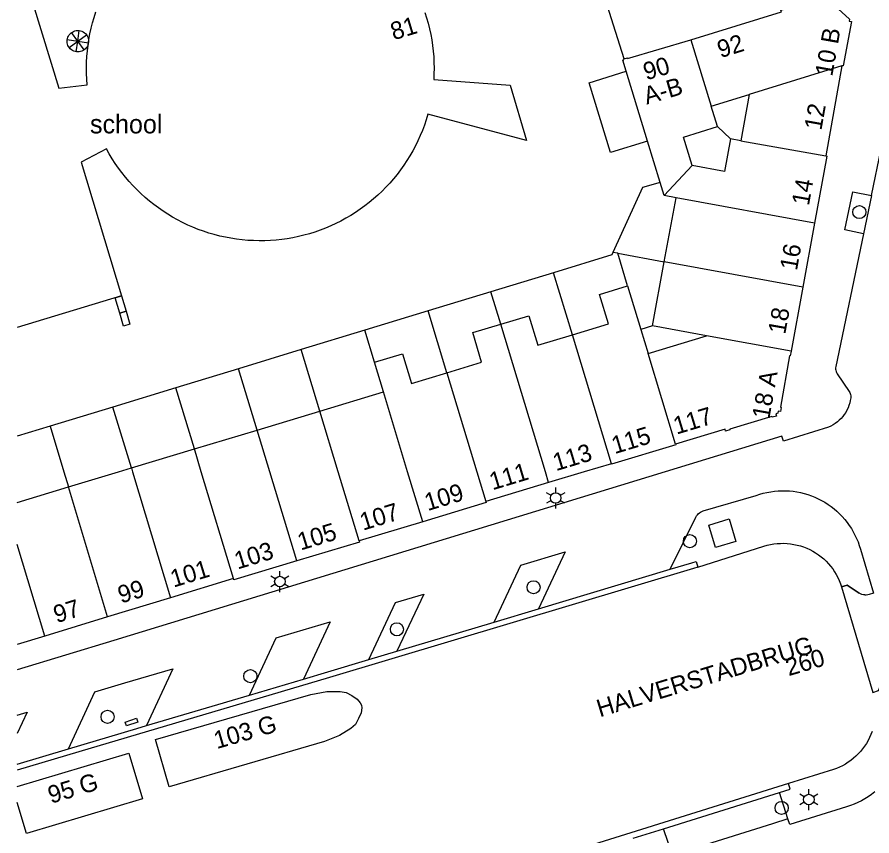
# Model space of a CAD drawing. Extents: x 122462 to 123306, y 485548 to 486417.
# Drawn here: x 122462 to 122535, y 486218.9 to 486288.9 of the extents above; entities that cross this region are included whole.
import ezdxf

# ---------------------------------------------------------------- set-up
doc = ezdxf.new("R2010")
doc.units = 0
for name, color, linetype in [('B-WE-IE-MEUBILAIR_WEGMEUBILAIR_VERKEERSBORD-S', 7, 'Continuous'), ('Level 1', 7, 'Continuous'), ('Level 10', 7, 'Continuous'), ('Level 12', 7, 'Continuous'), ('Level 14', 7, 'Continuous'), ('Level 15', 7, 'Continuous'), ('Level 17', 7, 'Continuous'), ('Level 19', 7, 'Continuous'), ('Level 2', 7, 'Continuous'), ('Level 21', 7, 'Continuous'), ('Level 32', 7, 'Continuous'), ('Level 33', 7, 'Continuous'), ('Level 4', 7, 'Continuous'), ('Level 40', 7, 'Continuous'), ('Level 50', 7, 'Continuous'), ('Level 53', 7, 'Continuous'), ('Level 62', 7, 'Continuous'), ('N meubilair putkast', 7, 'Continuous'), ('N werkgrens', 7, 'Continuous')]:
    doc.layers.add(name, color=color, linetype=linetype)

msp = doc.modelspace()

# ---------------------------------------------------------------- linework, layer by layer
at = {"layer": 'Level 1'}
for p, q in [((122532.48, 486284.697), (122531.091, 486276.988)), ((122521.32, 486281.241), (122524.568, 486282.25)), ((122524.568, 486282.25), (122523.855, 486278.292)), ((122521.859, 486279.506), (122521.32, 486281.241)), ((122516.965, 486274.72), (122515.878, 486278.265)), ((122523.855, 486278.292), (122522.953, 486278.455)), ((122517.308, 486273.601), (122516.965, 486274.72)), ((122517.303, 486267.945), (122518.31, 486273.417)), ((122518.31, 486273.417), (122517.308, 486273.601)), ((122530.14, 486271.239), (122529.132, 486265.768)), ((122516.296, 486262.474), (122517.303, 486267.945)), ((122514.176, 486265.888), (122515.298, 486262.173)), ((122529.132, 486265.768), (122528.13, 486260.319)), ((122520.897, 486261.627), (122516.296, 486262.474)), ((122515.298, 486262.173), (122515.917, 486260.122)), ((122515.917, 486260.122), (122520.897, 486261.627)), ((122493.317, 486256.833), (122492.554, 486259.36)), ((122487.892, 486255.195), (122493.317, 486256.833)), ((122482.53, 486253.576), (122487.892, 486255.195)), ((122477.168, 486251.957), (122482.53, 486253.576)), ((122471.79, 486250.333), (122477.168, 486251.957)), ((122466.413, 486248.711), (122470.686, 486250)), ((122470.686, 486250), (122471.79, 486250.333)), ((122510.47, 486250), (122507.426, 486249.085)), ((122512.785, 486250.696), (122510.47, 486250)), ((122462.03, 486247.387), (122466.413, 486248.711)), ((122507.426, 486249.085), (122502.059, 486247.469)), ((122496.669, 486245.738), (122491.245, 486244.097)), ((122480.519, 486240.89), (122475.139, 486239.25)), ((122475.139, 486239.25), (122469.765, 486237.61)), ((122469.765, 486237.61), (122464.39, 486235.969)), ((122464.39, 486235.969), (122462.03, 486235.259))]:
    msp.add_line(p, q, dxfattribs=at)
for points in [[(122519.559, 486286.91), (122527.317, 486289.297), (122527.269, 486289.449), (122530.959, 486290.59), (122531.009, 486290.409), (122531.189, 486290.459), (122533.12, 486288.679), (122533.098, 486288.51), (122533.289, 486288.479), (122532.58, 486284.679), (122532.48, 486284.697)], [(122463.413, 486289.945), (122465.586, 486282.778), (122468.027, 486283.078), (122467.989, 486283.562), (122467.967, 486284.046), (122467.96, 486284.531), (122467.97, 486285.016), (122467.995, 486285.501), (122468.036, 486285.984), (122468.093, 486286.466), (122468.166, 486286.946), (122468.254, 486287.423), (122468.358, 486287.896), (122468.477, 486288.367), (122468.612, 486288.833), (122468.761, 486289.294)], [(122496.856, 486289.255), (122497.004, 486288.793), (122497.137, 486288.326), (122497.255, 486287.856), (122497.358, 486287.382), (122497.445, 486286.904), (122497.516, 486286.425), (122497.572, 486285.943), (122497.611, 486285.459), (122497.635, 486284.975)], [(122513.879, 486285.284), (122514.149, 486285.363), (122514.16, 486285.324), (122519.559, 486286.91)], [(122514.051, 486284.225), (122513.758, 486285.18), (122513.846, 486285.207), (122513.83, 486285.269), (122513.879, 486285.284)], [(122497.635, 486284.975), (122497.643, 486284.49), (122497.636, 486284.005), (122497.612, 486283.52), (122504.133, 486283.027), (122505.539, 486278.306), (122497.114, 486280.554), (122496.974, 486280.091), (122496.819, 486279.633), (122496.649, 486279.18), (122496.465, 486278.732), (122496.266, 486278.291), (122496.052, 486277.857), (122495.825, 486277.43), (122495.584, 486277.01), (122495.33, 486276.599), (122495.062, 486276.196), (122494.782, 486275.802), (122494.489, 486275.417), (122494.183, 486275.042), (122493.865, 486274.677), (122493.536, 486274.322), (122493.196, 486273.979), (122492.844, 486273.647), (122492.482, 486273.326), (122492.109, 486273.017), (122491.727, 486272.721), (122491.335, 486272.437), (122490.935, 486272.166), (122490.525, 486271.908), (122490.108, 486271.663), (122489.683, 486271.432), (122489.25, 486271.216), (122488.811, 486271.013), (122488.365, 486270.825), (122487.914, 486270.651), (122487.457, 486270.492), (122486.995, 486270.348), (122486.529, 486270.219), (122486.058, 486270.105), (122485.585, 486270.007), (122485.108, 486269.924), (122484.629, 486269.856), (122484.148, 486269.804), (122483.665, 486269.768), (122483.182, 486269.748), (122482.698, 486269.743), (122482.215, 486269.754), (122481.732, 486269.781), (122481.25, 486269.823), (122480.769, 486269.881), (122480.291, 486269.954), (122479.816, 486270.043), (122479.343, 486270.148), (122478.874, 486270.267), (122478.41, 486270.402), (122477.95, 486270.552), (122477.495, 486270.717), (122477.046, 486270.896), (122476.603, 486271.09), (122476.166, 486271.299), (122475.736, 486271.521), (122475.314, 486271.757), (122474.9, 486272.007), (122474.494, 486272.27), (122474.096, 486272.546), (122473.708, 486272.835), (122473.33, 486273.136), (122472.961, 486273.45), (122472.603, 486273.775), (122472.256, 486274.112), (122471.92, 486274.46), (122471.595, 486274.818), (122471.282, 486275.187), (122470.981, 486275.566), (122470.693, 486275.955), (122470.417, 486276.352), (122470.155, 486276.759), (122469.906, 486277.173), (122469.67, 486277.596), (122467.513, 486276.461), (122470.948, 486265.029), (122462.03, 486262.345)], [(122515.878, 486278.265), (122512.706, 486277.292), (122510.879, 486283.252), (122514.051, 486284.225)], [(122519.691, 486276.162), (122518.934, 486278.598), (122521.859, 486279.506)], [(122522.953, 486278.455), (122522.437, 486275.656), (122519.691, 486276.162)], [(122531.091, 486276.988), (122531.189, 486276.969), (122530.14, 486271.239)], [(122509.459, 486261.707), (122512.546, 486262.639), (122511.783, 486265.166), (122514.176, 486265.888)], [(122503.337, 486262.616), (122505.731, 486263.339), (122506.494, 486260.812), (122509.459, 486261.707)], [(122498.742, 486258.472), (122501.707, 486259.367), (122500.944, 486261.894), (122503.337, 486262.616)], [(122528.13, 486260.319), (122528.056, 486259.908), (122527.997, 486259.918), (122527.22, 486255.518), (122527.28, 486255.508), (122527.219, 486255.16), (122527.02, 486255.194), (122526.989, 486255.019), (122526.82, 486254.969), (122526.88, 486254.769), (122526.512, 486254.661), (122526.495, 486254.718), (122522.897, 486253.658), (122522.914, 486253.6), (122522.539, 486253.489), (122522.493, 486253.645), (122518.258, 486252.369)], [(122492.554, 486259.36), (122494.948, 486260.083), (122495.71, 486257.556), (122498.742, 486258.472)], [(122518.258, 486252.369), (122518.279, 486252.299), (122512.799, 486250.65), (122512.785, 486250.696)], [(122502.059, 486247.469), (122502.1, 486247.38), (122496.669, 486245.738)], [(122491.245, 486244.097), (122491.269, 486244.009), (122485.908, 486242.397)], [(122485.908, 486242.397), (122480.539, 486240.779), (122480.519, 486240.89)]]:
    msp.add_lwpolyline(points, dxfattribs=at)
at = {"layer": 'Level 10'}
msp.add_lwpolyline([(122470.797, 486263.57), (122470.407, 486264.866), (122470.948, 486265.029), (122471.336, 486263.732), (122470.797, 486263.57)], dxfattribs=at)
at = {"layer": 'Level 12'}
for points in [[(122475.029, 486223.104), (122473.857, 486227.137), (122487.115, 486230.989), (122488.483, 486231.23), (122489.62, 486231.249), (122490.126, 486231.156), (122490.627, 486230.89), (122491.084, 486230.586), (122491.342, 486230.271), (122491.44, 486230.059), (122491.47, 486229.831), (122491.422, 486229.424), (122491.199, 486228.922), (122490.918, 486228.43), (122490.541, 486228.08), (122489.571, 486227.486), (122488.287, 486226.956), (122475.029, 486223.104)], [(122462.03, 486223.12), (122471.559, 486225.979), (122472.732, 486222.071), (122462.826, 486219.1)], [(122462.826, 486219.1), (122462.03, 486221.754)]]:
    msp.add_lwpolyline(points, dxfattribs=at)
at = {"layer": 'Level 14'}
msp.add_line((122535.166, 486239.635), (122534.803, 486239.523), dxfattribs=at)
for points in [[(122520.181, 486241.871), (122525.811, 486243.652), (122526.087, 486243.731), (122526.367, 486243.795), (122526.651, 486243.844), (122526.936, 486243.877), (122527.223, 486243.895), (122527.51, 486243.897), (122527.798, 486243.883), (122528.083, 486243.854), (122528.367, 486243.809), (122528.648, 486243.749), (122528.926, 486243.674), (122529.199, 486243.583), (122529.466, 486243.478), (122529.728, 486243.359), (122529.982, 486243.226), (122530.229, 486243.079), (122530.468, 486242.918), (122530.697, 486242.745), (122530.917, 486242.56), (122531.126, 486242.363), (122531.324, 486242.155), (122531.511, 486241.936), (122531.686, 486241.708), (122531.847, 486241.47), (122531.996, 486241.224), (122532.131, 486240.971), (122532.252, 486240.71), (122532.359, 486240.443), (122532.451, 486240.171)], [(122532.451, 486240.171), (122532.928, 486240.318), (122533.961, 486239.642)], [(122534.307, 486239.499), (122534.186, 486239.532), (122534.07, 486239.58), (122533.961, 486239.642)], [(122534.556, 486239.48), (122534.431, 486239.482), (122534.307, 486239.499)], [(122534.803, 486239.523), (122534.681, 486239.494), (122534.556, 486239.48)], [(122535.056, 486227.825), (122534.955, 486227.561), (122534.84, 486227.303), (122534.711, 486227.051), (122534.569, 486226.806), (122534.414, 486226.57), (122534.247, 486226.342), (122534.067, 486226.123), (122533.877, 486225.914), (122533.675, 486225.716), (122533.463, 486225.528), (122533.242, 486225.353), (122533.011, 486225.189), (122532.772, 486225.038), (122532.525, 486224.899), (122532.272, 486224.774), (122532.012, 486224.663), (122531.746, 486224.566), (122527.912, 486223.366)]]:
    msp.add_lwpolyline(points, dxfattribs=at)
at = {"layer": 'Level 15'}
for p, q in [((122506.559, 486238.305), (122517.814, 486241.678)), ((122502.776, 486237.171), (122506.559, 486238.305)), ((122494.473, 486234.683), (122502.776, 486237.171)), ((122492.077, 486233.964), (122494.473, 486234.683)), ((122481.887, 486230.934), (122486.49, 486232.297)), ((122473.078, 486228.324), (122481.887, 486230.934)), ((122462.03, 486225.029), (122466.426, 486226.35)), ((122517.245, 486219.506), (122527.154, 486222.605)), ((122514.659, 486218.698), (122517.245, 486219.506))]:
    msp.add_line(p, q, dxfattribs=at)
for points in [[(122517.814, 486241.678), (122519.654, 486242.229), (122520.038, 486242.351), (122520.181, 486241.871)], [(122520.181, 486241.871), (122519.801, 486241.751), (122488.701, 486232.431), (122467.301, 486226.091), (122462.03, 486224.507)], [(122486.49, 486232.297), (122488.558, 486232.91), (122492.077, 486233.964)], [(122466.426, 486226.35), (122472.248, 486228.078), (122473.078, 486228.324)], [(122527.912, 486223.366), (122462.03, 486202.764)], [(122527.154, 486222.605), (122528.061, 486222.889), (122527.912, 486223.366)]]:
    msp.add_lwpolyline(points, dxfattribs=at)
at = {"layer": 'Level 17'}
for p, q in [((122534.996, 486273.611), (122536.658, 486281.588)), ((122534.996, 486273.611), (122534.315, 486270.338)), ((122527.863, 486220.367), (122527.154, 486222.605)), ((122518.019, 486217.267), (122517.245, 486219.506))]:
    msp.add_line(p, q, dxfattribs=at)
for points in [[(122534.315, 486270.338), (122532.734, 486270.667), (122533.415, 486273.94), (122534.996, 486273.611)], [(122534.315, 486270.338), (122531.953, 486258.998), (122531.938, 486258.893), (122531.937, 486258.787), (122531.951, 486258.682), (122531.978, 486258.58), (122532.018, 486258.482), (122532.071, 486258.39), (122533.093, 486256.862), (122533.141, 486256.78), (122533.179, 486256.694), (122533.207, 486256.603), (122533.223, 486256.51), (122533.229, 486256.415), (122533.223, 486256.321), (122533.189, 486256.104), (122533.141, 486255.891), (122533.077, 486255.681), (122532.999, 486255.477), (122532.906, 486255.278), (122532.8, 486255.086), (122532.681, 486254.902), (122532.549, 486254.727), (122532.405, 486254.562), (122532.25, 486254.407), (122532.085, 486254.264), (122531.91, 486254.132), (122531.726, 486254.013), (122531.534, 486253.907), (122531.335, 486253.815), (122527.48, 486252.621), (122527.351, 486253.043), (122517.392, 486250)], [(122517.392, 486250), (122470.287, 486235.607), (122462.03, 486233.084)], [(122517.814, 486241.678), (122519.998, 486246.142), (122520.056, 486246.245), (122520.127, 486246.341), (122520.208, 486246.428), (122520.299, 486246.505), (122520.398, 486246.57), (122520.504, 486246.623), (122520.616, 486246.663), (122525.15, 486247.985), (122525.454, 486248.087), (122525.763, 486248.175), (122526.076, 486248.248), (122526.392, 486248.307), (122526.71, 486248.35), (122527.03, 486248.379), (122527.35, 486248.392), (122527.671, 486248.391), (122527.992, 486248.374), (122528.312, 486248.342), (122528.629, 486248.295), (122528.944, 486248.233), (122529.256, 486248.157), (122529.564, 486248.066), (122529.867, 486247.961), (122530.165, 486247.841), (122530.457, 486247.708), (122530.743, 486247.561), (122531.021, 486247.4), (122531.292, 486247.227), (122531.553, 486247.042), (122531.806, 486246.844), (122532.05, 486246.634), (122532.283, 486246.414), (122532.506, 486246.182), (122532.717, 486245.94), (122532.917, 486245.689), (122533.105, 486245.429), (122533.28, 486245.16), (122533.443, 486244.883), (122533.592, 486244.599), (122533.728, 486244.308), (122533.85, 486244.011), (122533.957, 486243.708), (122534.051, 486243.401), (122535.166, 486239.635)], [(122502.776, 486237.171), (122505.048, 486242.029), (122508.834, 486243.155), (122506.559, 486238.305)], [(122535.166, 486239.635), (122534.803, 486239.523), (122534.681, 486239.494), (122534.556, 486239.48), (122534.431, 486239.481), (122534.307, 486239.499), (122534.186, 486239.532), (122534.07, 486239.58), (122533.961, 486239.642), (122532.928, 486240.318), (122532.451, 486240.171), (122535.121, 486231.161), (122535.598, 486231.309), (122536.095, 486232.466), (122536.151, 486232.576), (122536.22, 486232.679), (122536.301, 486232.772), (122536.393, 486232.854), (122536.494, 486232.925), (122536.603, 486232.982), (122536.719, 486233.026), (122537.09, 486233.14)], [(122492.077, 486233.964), (122494.361, 486238.848), (122496.757, 486239.561), (122494.473, 486234.683)], [(122481.887, 486230.934), (122484.154, 486235.81), (122488.754, 486237.18), (122486.49, 486232.297)], [(122466.426, 486226.35), (122468.675, 486231.204), (122471.235, 486231.966), (122475.336, 486233.186), (122473.078, 486228.324)], [(122462.03, 486229.226), (122462.876, 486229.478), (122462.03, 486227.648)], [(122535.284, 486222.651), (122535.01, 486222.445), (122534.727, 486222.251), (122534.435, 486222.07), (122534.136, 486221.903), (122533.829, 486221.75), (122533.515, 486221.61), (122533.195, 486221.486), (122532.87, 486221.376), (122528.023, 486219.86), (122527.863, 486220.367)], [(122527.863, 486220.367), (122526.548, 486219.939), (122518.019, 486217.267)]]:
    msp.add_lwpolyline(points, dxfattribs=at)
at = {"layer": 'Level 19'}
for p, q in [((122522.953, 486278.455), (122521.859, 486279.506)), ((122513.334, 486268.674), (122512.923, 486268.75)), ((122513.334, 486268.674), (122517.303, 486267.945)), ((122514.176, 486265.888), (122513.334, 486268.674)), ((122509.459, 486261.707), (122507.856, 486267.018)), ((122503.337, 486262.616), (122502.501, 486265.385)), ((122498.742, 486258.472), (122497.147, 486263.753)), ((122516.296, 486262.474), (122515.298, 486262.173)), ((122492.554, 486259.36), (122491.726, 486262.1)), ((122487.892, 486255.195), (122486.305, 486260.448)), ((122482.53, 486253.576), (122480.948, 486258.815)), ((122477.168, 486251.957), (122475.59, 486257.181)), ((122471.79, 486250.333), (122470.217, 486255.543)), ((122464.842, 486253.905), (122466.023, 486250)), ((122466.023, 486250), (122466.413, 486248.711))]:
    msp.add_line(p, q, dxfattribs=at)
at = {"layer": 'Level 2'}
msp.add_lwpolyline([(122521.691, 486243.544), (122521.112, 486245.457), (122522.835, 486245.978), (122523.414, 486244.065), (122521.691, 486243.544)], dxfattribs=at)
at = {"layer": 'Level 21'}
msp.add_lwpolyline([(122471.13, 486262.462), (122470.797, 486263.57), (122471.336, 486263.732), (122471.67, 486262.624), (122471.13, 486262.462)], dxfattribs=at)
at = {"layer": 'Level 32'}
msp.add_lwpolyline([(122467.215, 486285.876), (122467.097, 486285.885), (122466.98, 486285.908), (122466.868, 486285.946), (122466.761, 486285.999), (122466.662, 486286.064), (122466.573, 486286.142), (122466.494, 486286.231), (122466.427, 486286.329), (122466.374, 486286.435), (122466.334, 486286.547), (122466.31, 486286.663), (122466.3, 486286.782), (122466.306, 486286.9), (122466.327, 486287.017), (122466.363, 486287.13), (122466.413, 486287.238), (122466.479, 486287.339), (122466.558, 486287.431), (122466.648, 486287.511), (122466.748, 486287.579), (122466.856, 486287.634), (122466.971, 486287.673), (122467.089, 486287.698), (122467.21, 486287.707), (122467.33, 486287.7), (122467.449, 486287.677), (122467.564, 486287.639), (122467.673, 486287.586), (122467.774, 486287.52), (122467.865, 486287.441), (122467.945, 486287.35), (122468.013, 486287.25), (122468.067, 486287.142), (122468.107, 486287.028), (122468.131, 486286.91), (122468.14, 486286.789), (122468.103, 486286.538), (122468.062, 486286.426), (122468.008, 486286.321), (122467.94, 486286.224), (122467.86, 486286.136), (122467.77, 486286.059), (122467.67, 486285.994), (122467.563, 486285.943), (122467.45, 486285.906), (122467.334, 486285.883), (122467.215, 486285.876)], dxfattribs=at)
at = {"layer": 'Level 33'}
for points in [[(122466.478, 486286.249), (122467.21, 486286.797), (122467.949, 486287.343)], [(122467.758, 486286.061), (122467.21, 486286.797), (122466.667, 486287.526)], [(122467.079, 486285.892), (122467.21, 486286.797), (122467.344, 486287.697)], [(122466.307, 486286.93), (122467.21, 486286.797), (122468.121, 486286.663)]]:
    msp.add_lwpolyline(points, dxfattribs=at)
at = {"layer": 'Level 4'}
for p, q in [((122519.559, 486286.91), (122521.32, 486281.241)), ((122532.48, 486284.697), (122524.568, 486282.25)), ((122515.878, 486278.265), (122514.051, 486284.225)), ((122523.855, 486278.292), (122531.091, 486276.988)), ((122517.308, 486273.601), (122519.691, 486276.162)), ((122530.14, 486271.239), (122518.31, 486273.417)), ((122529.132, 486265.768), (122517.303, 486267.945)), ((122507.149, 486250), (122503.337, 486262.616)), ((122512.785, 486250.696), (122509.459, 486261.707)), ((122528.13, 486260.319), (122520.897, 486261.627)), ((122518.258, 486252.369), (122515.917, 486260.122)), ((122495.381, 486250), (122493.317, 486256.833)), ((122489.462, 486250), (122487.892, 486255.195)), ((122483.611, 486250), (122482.53, 486253.576)), ((122477.761, 486250), (122477.168, 486251.957)), ((122471.79, 486250.333), (122471.891, 486250)), ((122471.891, 486250), (122475.139, 486239.25)), ((122480.519, 486240.89), (122477.761, 486250)), ((122485.908, 486242.397), (122483.611, 486250)), ((122491.245, 486244.097), (122489.462, 486250)), ((122496.669, 486245.738), (122495.381, 486250)), ((122507.426, 486249.085), (122507.149, 486250)), ((122469.765, 486237.61), (122466.413, 486248.711)), ((122464.39, 486235.969), (122462.03, 486243.79))]:
    msp.add_line(p, q, dxfattribs=at)
for points in [[(122498.742, 486258.472), (122501.302, 486250)], [(122501.302, 486250), (122501.302, 486249.999), (122502.059, 486247.469)]]:
    msp.add_lwpolyline(points, dxfattribs=at)
at = {"layer": 'Level 40'}
msp.add_lwpolyline([(122471.378, 486228.297), (122471.269, 486228.625), (122472.236, 486228.945), (122472.345, 486228.617), (122471.378, 486228.297)], dxfattribs=at)
at = {"layer": 'Level 50'}
for p, q in [((122508.031, 486248.221), (122508.031, 486248.671)), ((122507.641, 486247.996), (122507.251, 486248.221)), ((122508.81, 486248.221), (122508.42, 486247.996)), ((122507.641, 486247.546), (122507.251, 486247.321)), ((122508.031, 486246.871), (122508.031, 486247.321)), ((122508.81, 486247.321), (122508.42, 486247.546)), ((122484.472, 486241.081), (122484.472, 486241.531)), ((122484.082, 486240.856), (122483.692, 486241.081)), ((122485.251, 486241.081), (122484.861, 486240.856)), ((122484.082, 486240.406), (122483.692, 486240.181)), ((122484.472, 486239.731), (122484.472, 486240.181)), ((122485.251, 486240.181), (122484.861, 486240.406)), ((122529.261, 486222.228), (122528.871, 486222.453)), ((122529.651, 486222.453), (122529.651, 486222.903)), ((122530.43, 486222.453), (122530.04, 486222.228)), ((122529.261, 486221.778), (122528.871, 486221.553)), ((122529.651, 486221.103), (122529.651, 486221.553)), ((122530.43, 486221.553), (122530.04, 486221.778))]:
    msp.add_line(p, q, dxfattribs=at)
for centre in [(122508.031, 486247.771), (122484.472, 486240.631), (122529.651, 486222.003)]:
    msp.add_circle(centre, 0.45, dxfattribs=at)
at = {"layer": 'Level 53'}
for centre in [(122533.963, 486272.196), (122519.492, 486244.081), (122506.141, 486240.141), (122494.472, 486236.551), (122481.951, 486232.551), (122469.761, 486229.071), (122527.327, 486221.29)]:
    msp.add_circle(centre, 0.56, dxfattribs=at)
at = {"layer": 'N werkgrens'}
for p, q in [((122507.856, 486267.018), (122502.501, 486265.385)), ((122502.501, 486265.385), (122497.147, 486263.753)), ((122497.147, 486263.753), (122491.726, 486262.1)), ((122491.726, 486262.1), (122486.305, 486260.448)), ((122486.305, 486260.448), (122480.948, 486258.815)), ((122480.948, 486258.815), (122475.59, 486257.181)), ((122475.59, 486257.181), (122470.217, 486255.543)), ((122470.217, 486255.543), (122464.842, 486253.905)), ((122464.842, 486253.905), (122462.03, 486253.055))]:
    msp.add_line(p, q, dxfattribs=at)
for points in [[(122513.879, 486285.284), (122509.718, 486298.443), (122512.922, 486299.468)], [(122516.965, 486274.72), (122515.451, 486274.283), (122512.923, 486268.75)], [(122512.923, 486268.75), (122512.823, 486268.532), (122507.856, 486267.018)]]:
    msp.add_lwpolyline(points, dxfattribs=at)

# ---------------------------------------------------------------- texts
at = {"layer": 'B-WE-IE-MEUBILAIR_WEGMEUBILAIR_VERKEERSBORD-S'}
for s, rotation, p in [('81', 16.75372, (122494.19, 486286.871)), ('92', 17.09912, (122522.104, 486285.34)), ('10 B', 79.93082, (122531.645, 486283.736)), ('90', 16.37059, (122515.764, 486283.442)), ('A-B', 16.36469, (122515.801, 486281.373)), ('12', 79.93082, (122530.719, 486279.122)), ('14', 79.93082, (122529.653, 486272.696)), ('16', 79.93082, (122528.633, 486267.146)), ('18', 79.93082, (122527.632, 486261.702)), ('18 A', 79.93082, (122526.268, 486254.439)), ('117', 16.76742, (122518.347, 486253.18)), ('115', 16.76742, (122513.067, 486251.514)), ('113', 16.76742, (122508.051, 486250.056)), ('111', 16.75703, (122502.63, 486248.424)), ('109', 16.97597, (122497.093, 486246.645)), ('107', 16.97597, (122491.572, 486244.974)), ('105', 16.97597, (122486.246, 486243.275)), ('103', 16.97597, (122480.856, 486241.653)), ('101', 16.97597, (122475.39, 486240.11)), ('99', 16.96294, (122470.902, 486238.743)), ('97', 16.96294, (122465.403, 486237.064)), ('103 G', 16.20078, (122479.087, 486226.313)), ('95 G', 16.7019, (122464.927, 486221.64))]:
    msp.add_text(s, height=1.5, rotation=rotation, dxfattribs=at).set_placement(p)
at = {"layer": 'Level 62'}
msp.add_text('school', height=1.6, dxfattribs=at).set_placement((122468.256, 486278.919))
at = {"layer": 'N meubilair putkast'}
for s, rotation, p in [('HALVERSTADBRUG', 16.81669, (122511.797, 486229.028)), ('260', 16.50497, (122527.931, 486232.543))]:
    msp.add_text(s, height=1.5, rotation=rotation, dxfattribs=at).set_placement(p)

doc.saveas('drawing.dxf')
